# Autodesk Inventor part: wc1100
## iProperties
Shininess: 64.0
Length Units: 11272
Angle Units: 11279
Time Units: 11290
Mass Units: 11286
Length Display Precision: 3
Angle Display Precision: 2
Compacted: True
Part Number: wc1100
Document SubType Name: Modeling
Created: 2004-08
Designer: John Blackburn
Manufacturer: Standard
Standards Organization: Custom
Material: Aluminum-6061
Density: 0.0
Volumn: 0.0
Area: 0.0
PropertySet Name: Model Information
Control State: 0
Master: False
Checked Out: False
Author: John Blackburn
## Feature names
1. Base1
